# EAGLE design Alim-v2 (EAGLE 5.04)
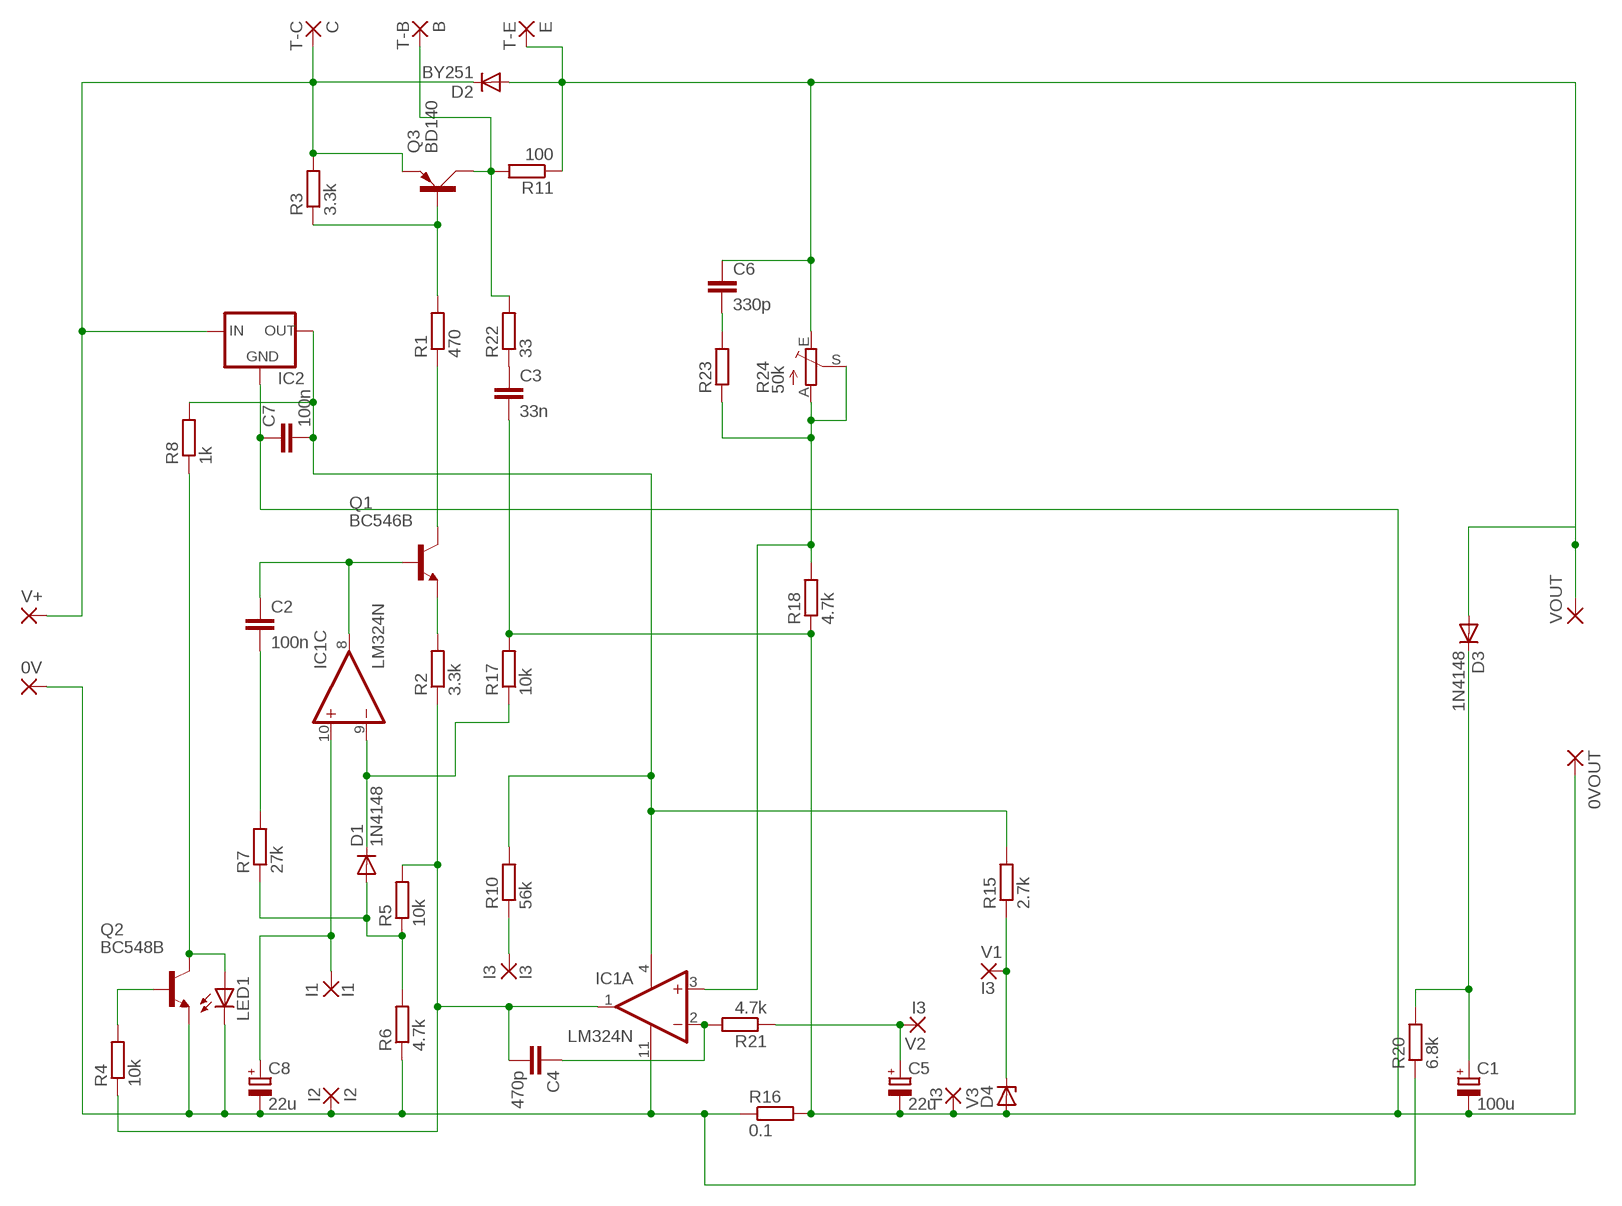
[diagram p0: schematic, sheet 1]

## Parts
0V  3,81/1,4  [3,81/1,4]
0VOUT  3,81/1,4  [3,81/1,4]
B  T-B  WIREPAD3,81/1,4  [3,81/1,4]
C  T-C  WIREPAD3,81/1,4  [3,81/1,4]
C1  100u  CPOL-EUE2.5-5  [E2,5-5]
C2  100n  C-EU025-025X050  [C025-025X050]
C3  33n  C-EU025-025X050  [C025-025X050]
C4  470p  C-EU025-025X050  [C025-025X050]
C5  22u  CPOL-EUE2.5-5  [E2,5-5]
C6  330p  C-EU025-025X050  [C025-025X050]
C7  100n  C-EU025-025X050  [C025-025X050]
C8  22u  CPOL-EUE2.5-5  [E2,5-5]
D1  1N4148  1N4148DO35-10  [DO35-10]
D2  BY251  [DO201-15]
D3  1N4148  1N4148DO35-10  [DO35-10]
D4  ZENER-DIODEDO41Z10  [DO41Z10]
E  T-E  WIREPAD3,81/1,4  [3,81/1,4]
I1  I1  WIREPAD1,6/0,9  [1,6/0,9]
I2  I2  WIREPAD1,6/0,9  [1,6/0,9]
I3  I3  WIREPAD1,6/0,9  [1,6/0,9]
IC1  LM324N  [DIL14]
IC2  78LXX  [78LXX]
LED1  LED5MM  [LED5MM]
Q1  BC546B  [TO92-EBC]
Q2  BC548B  [TO92-EBC]
Q3  BD140  [TO126AV]
R1  470  R-EU_0207/10  [0207/10]
R2  3.3k  R-EU_0207/10  [0207/10]
R3  3.3k  R-EU_0207/10  [0207/10]
R4  10k  R-EU_0207/10  [0207/10]
R5  10k  R-EU_0207/10  [0207/10]
R6  4.7k  R-EU_0207/10  [0207/10]
R7  27k  R-EU_0207/10  [0207/10]
R8  1k  R-EU_0207/10  [0207/10]
R10  56k  R-EU_0207/10  [0207/10]
R11  100  R-EU_0207/10  [0207/10]
R15  2.7k  R-EU_0207/10  [0207/10]
R16  0.1  R-EU_0617/5V  [0617V]
R17  10k  R-EU_0207/10  [0207/10]
R18  4.7k  R-EU_0207/10  [0207/10]
R20  6.8k  R-EU_0207/10  [0207/10]
R21  4.7k  R-EU_0207/10  [0207/10]
R22  33  R-EU_0207/10  [0207/10]
R23  R-EU_0207/10  [0207/10]
R24  50k  TRIM_EU-B64Y  [B64Y]
V1  I3  WIREPAD1,6/0,9  [1,6/0,9]
V2  I3  WIREPAD1,6/0,9  [1,6/0,9]
V3  I3  WIREPAD1,6/0,9  [1,6/0,9]
V+  3,81/1,4  [3,81/1,4]
VOUT  3,81/1,4  [3,81/1,4]

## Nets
N$1: Q3.B R1.2 R3.1
N$2: Q1.C R1.1
N$3: Q1.E R2.2
N$5: Q2.B R4.2
N$6: C4.2 IC1.1(A:OUT) R2.1 R4.1 R5.2
N$7: D1.C IC1.9(C:-IN) R17.1
N$8: 0V.1(P) C8.- I2.1(P) IC1.11(P:V-) LED1.K(C) Q2.E R6.1 R16.1 R20.1
N$9: D1.A R5.1 R6.2 R7.1
N$10: LED1.A Q2.C R8.1
N$11: C.1(P) D2.C IC2.IN Q3.E R3.2 V+.1(P)
N$12: C2.1 IC1.8(C:OUT) Q1.B
N$13: C8.+ I1.1(P) IC1.10(C:+IN)
N$14: I3.1(P) R10.1
N$15: C7.2 IC1.4(P:V+) IC2.OUT R8.2 R10.2 R15.2
N$16: 0VOUT.1(P) C1.- C3.2 C5.- C7.1 D4.A IC2.GND R16.2 R17.2 R18.1 V3.1(P)
N$17: B.1(P) Q3.C R11.2 R22.2
N$18: C6.1 D2.A D3.A E.1(P) R11.1 R24.E VOUT.1(P)
N$20: D4.C R15.1 V1.1(P)
N$21: IC1.3(A:+IN) R18.2 R23.1 R24.A R24.S
N$22: C4.1 IC1.2(A:-IN) R21.2
N$23: C2.2 R7.2
N$25: C1.+ D3.C R20.2
N$26: C3.1 R22.1
N$27: C5.+ R21.1 V2.1(P)
N$29: C6.2 R23.2
Unconnected: IC1.5(B:+IN) IC1.6(B:-IN) IC1.7(B:OUT) IC1.12(D:+IN) IC1.13(D:-IN) IC1.14(D:OUT)

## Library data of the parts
0V 0VOUT V+ VOUT = wirepad:3,81/1,4: THROUGH-HOLE PAD
B C E I1-I3 V1-V3 = wirepad:WIREPAD: Wire PAD connect wire on PCB
C1 C5 C8 = rcl:CPOL-EU: POLARIZED CAPACITOR, European symbol
C2-C4 C6 C7 = rcl:C-EU: CAPACITOR, European symbol
D1 D3 = diode:1N4148: DIODE
D2 = diode:BY251: DIODE
D4 = diode:ZENER-DIODE: Z-Diode
IC1 = linear:LM324: OP AMP
IC2 = v-reg:78LXX: VOLTAGE REGULATOR
LED1 = led:LED: LED
Q1 = transistor-npn:BC546*: NPN Transistor
Q2 = transistor-npn:BC548*: NPN Transistor
Q3 = transistor-power:BD140: PNP TRANSISTOR
R1-R8 R10 R11 R15 R17 R18 R20-R23 = resistor:R-EU_: RESISTOR, European symbol
R16 = rcl:R-EU_: RESISTOR, European symbol
R24 = pot:TRIM_EU-: POTENTIOMETER

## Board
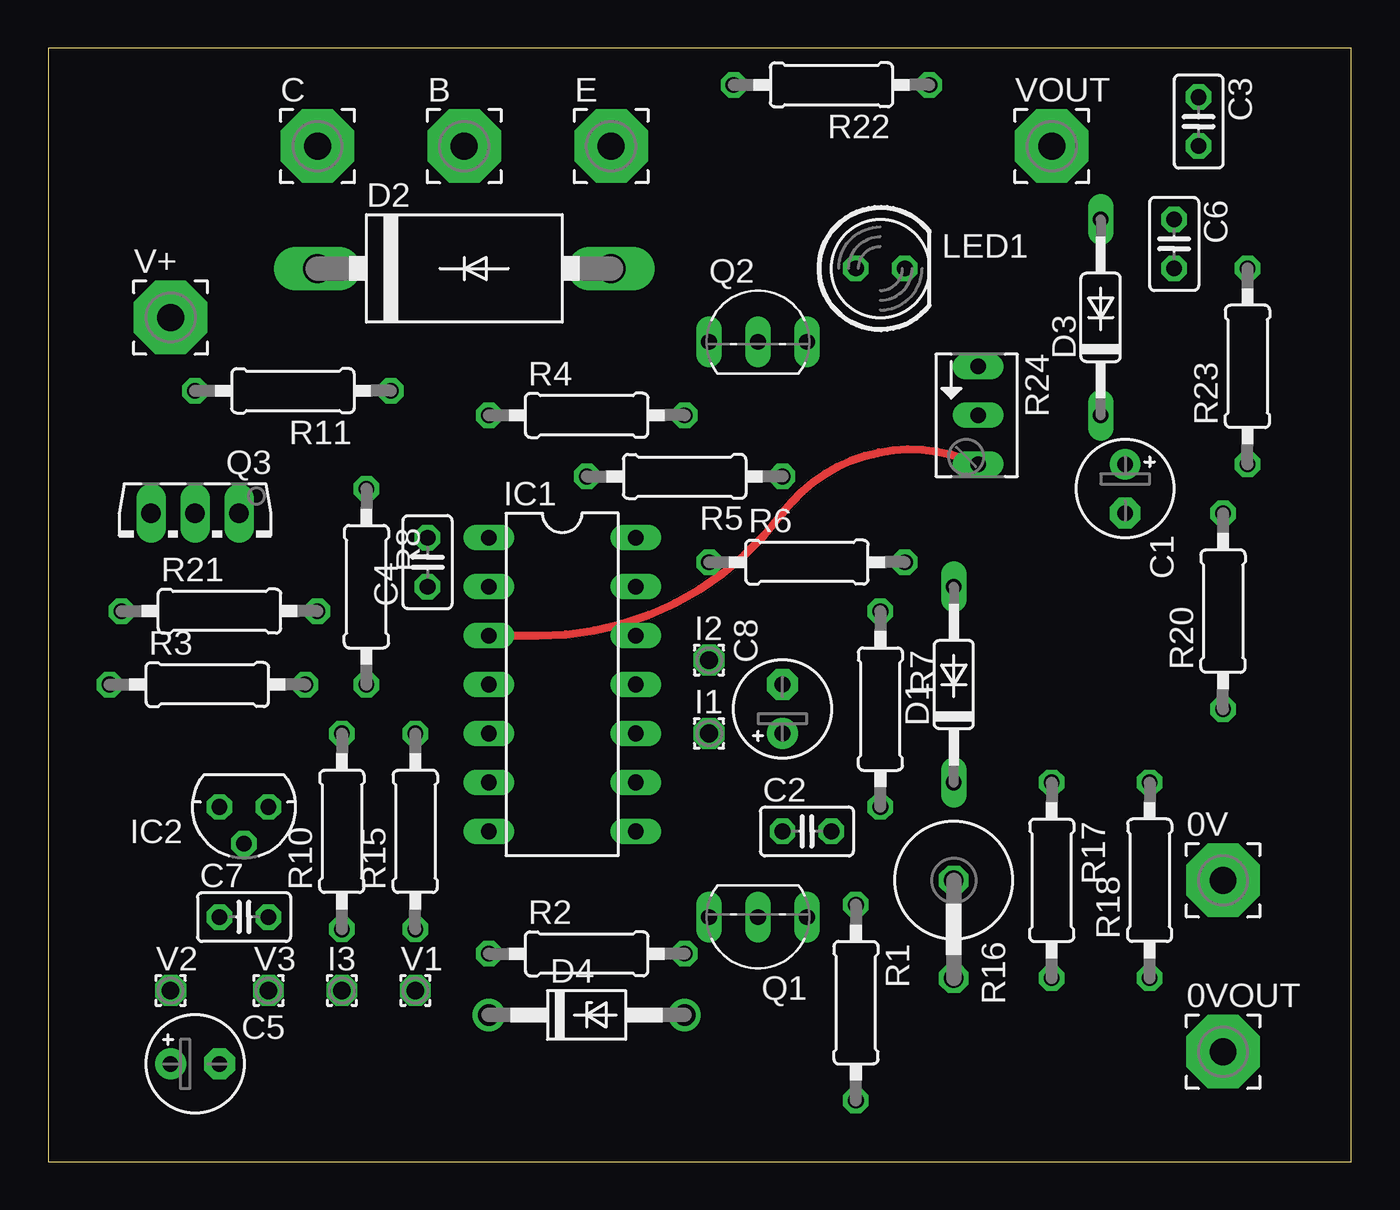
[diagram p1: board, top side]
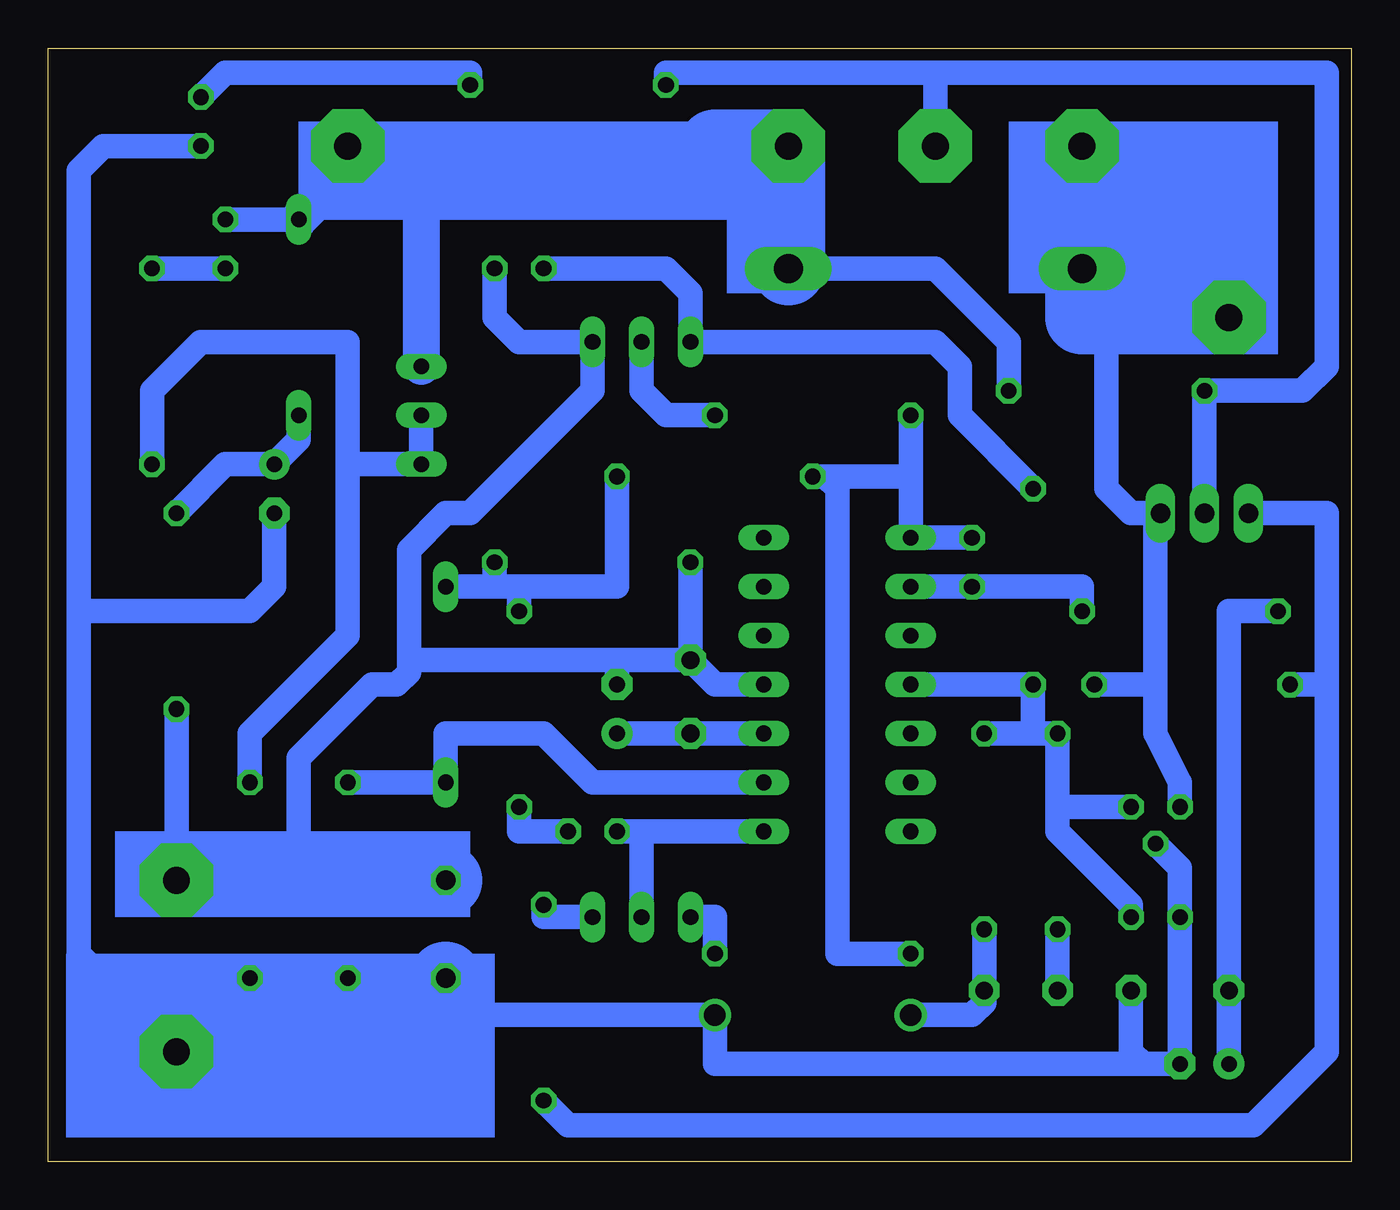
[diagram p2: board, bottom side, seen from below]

Size 67.61 x 57.77 mm. Coordinates in mm from the lower left corner, seen from the top.
Outline: 0,0 67.61,0 67.61,57.77 0,57.77 0,0
Copper layers (1*16): Top 0.035mm / dielectric 1.5mm / Bottom 0.035mm
Design rules "default": minimum track width 10mil, minimum drill 24mil, track to track 8mil, track to pad 8mil, pad to pad 8mil, via to via 8mil, smd to smd 8mil, copper to edge 40mil, drill to drill 8mil, minimum pad ring 10mil, minimum via ring 8mil, stop-mask expansion 4mil, vias tented up to drill 0mil, thermal gap 10mil

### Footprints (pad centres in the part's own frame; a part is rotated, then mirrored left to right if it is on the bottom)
3,81/1,4 = drill 1.397 pad 3.81 octagon: 1 0,0
E2,5-5 = drill 0.813 pad 1.6 round: + -1.27,0 | drill 0.813 pad 1.6 octagon: - 1.27,0
C025-025X050 = drill 0.813 octagon: 1 -1.27,0; 2 1.27,0
DO35-10 = drill 0.813 long: A 5.08,0; C -5.08,0
DO201-15 = drill 1.499 long: A 7.62,0; C -7.62,0
DO41Z10 = drill 1.118 round: A 5.08,0; C -5.08,0
1,6/0,9 = drill 0.914 pad 1.6 octagon: 1 0,0
DIL14 = drill 0.813 long: 1 -7.62,-3.81; 2 -5.08,-3.81; 3 -2.54,-3.81; 4 0,-3.81; 5 2.54,-3.81; 6 5.08,-3.81; 7 7.62,-3.81; 8 7.62,3.81; 9 5.08,3.81; 10 2.54,3.81; 11 0,3.81; 12 -2.54,3.81; 13 -5.08,3.81; 14 -7.62,3.81
78LXX = drill 0.813 octagon: GND 0,1.905; IN 1.27,0; OUT -1.27,0
LED5MM = drill 0.813 octagon: A -1.27,0; K 1.27,0
TO92-EBC = drill 0.813 long: B 0,-1.27; C -2.54,-1.27; E 2.54,-1.27
TO126AV = drill 1.016 long: B 2.286,-1.27; C 0,-1.27; E -2.286,-1.27
0207/10 = drill 0.813 octagon: 1 -5.08,0; 2 5.08,0
0617V = drill 1.016 octagon: 1 -2.54,0; 2 2.54,0
B64Y = drill 0.813 long: A 2.54,0; E -2.54,0; S 0,0

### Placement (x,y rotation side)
0V  60.96,14.6 0 top
0VOUT  60.96,5.71 0 top
B  21.59,52.71 0 top
C  13.97,52.71 0 top
C1  55.88,34.92 270 top
C2  39.37,17.14 0 top
C3  59.69,53.98 270 top
C4  19.68,31.12 90 top
C5  7.62,5.08 0 top
C6  58.42,47.62 270 top
C7  10.16,12.7 0 top
C8  38.1,23.49 90 top
D1  46.99,24.77 90 top
D2  21.59,46.35 0 top
D3  54.61,43.82 90 top
D4  27.94,7.62 0 top
E  29.21,52.71 0 top
I1  34.29,22.23 0 top
I2  34.29,26.03 0 top
I3  15.24,8.89 0 top
IC1  26.67,24.77 270 top
IC2  10.16,18.41 180 top
LED1  43.18,46.35 0 top
Q1  36.83,11.43 180 top
Q2  36.83,43.82 0 top
Q3  7.62,32.38 180 top
R1  41.91,8.25 270 top
R2  27.94,10.8 0 top
R3  8.26,24.77 0 top
R4  27.94,38.73 0 top
R5  33.02,35.56 180 top
R6  39.37,31.12 0 top
R7  43.18,23.49 270 top
R8  16.51,29.84 270 top
R10  15.24,17.14 90 top
R11  12.7,40 180 top
R15  19.05,17.14 90 top
R16  46.99,12.06 270 top
R17  52.07,14.6 270 top
R18  57.15,14.6 90 top
R20  60.96,28.57 90 top
R21  8.89,28.57 0 top
R22  40.64,55.88 180 top
R23  62.23,41.27 90 top
R24  48.26,38.73 270 top
V1  19.05,8.89 0 top
V2  6.35,8.89 0 top
V3  11.43,8.89 0 top
V+  6.35,43.82 0 top
VOUT  52.07,52.71 0 top

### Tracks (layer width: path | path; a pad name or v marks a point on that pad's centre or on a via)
N$1
  Bottom 1.27: Q3.B 1.27,33.66 1.27,24.77 | 1.27,24.77 R3.1 | 1.27,24.77 1.27,5.71 5.08,1.9 40.64,1.9 R1.2
N$2
  Bottom 1.27: Q1.C 41.91,12.7 R1.1
N$3
  Bottom 1.27: R2.2 33.02,12.7 Q1.E
N$5
  Bottom 1.27: R4.2 35.56,38.73 36.83,40 Q2.B
N$6
  Bottom 1.27: R2.1 26.67,10.8 26.67,34.92 27.3,35.56 R5.2 22.86,35.56 22.86,36.2 | 22.86,36.2 IC1.1 C4.2 | 22.86,36.2 R4.1
N$7
  Bottom 1.27: IC1.9 39.37,19.68 41.91,22.23 46.99,22.23 D1.C R17.1
N$8
  Bottom 1.27: LED1.K 44.45,43.82 43.18,42.54 Q2.E 39.37,40 45.72,33.66 46.99,33.66 48.9,31.75 48.9,26.03 | 0V.1 R20.1 | IC1.11 33.02,24.77 I2.1 | 54.61,14.6 54.61,20.95 50.8,24.77 49.53,24.77 48.9,25.4 48.9,26.03 | I2.1 R6.1 I2.1 | I2.1 38.1,26.03 | 38.1,26.03 48.9,26.03 | 38.1,26.03 C8.-
  Bottom 3.81: R16.1 54.61,14.6 0V.1
N$9
  Bottom 1.27: 43.18,29.84 R7.1 | 43.18,29.84 38.1,29.84 R5.1 | 43.18,29.84 44.45,29.84 | 44.45,29.84 D1.A | 44.45,29.84 R6.2
N$10
  Bottom 1.27: R8.1 20.32,38.73 20.32,41.27 21.59,42.54 Q2.C 34.29,45.09 35.56,46.35 LED1.A
N$11
  Bottom 1.27: IC2.IN 8.89,19.68 10.16,22.23 10.16,24.77 | 10.16,24.77 R3.2 | 10.16,24.77 10.16,33.4 Q3.E 11.43,33.66 12.7,34.92 12.7,43.82
  Bottom 3.81: V+.1 12.7,43.82 13.97,43.82 D2.C C.1
N$12
  Bottom 1.27: IC1.8 36.83,17.14 | 36.83,17.14 C2.1 | 36.83,17.14 Q1.B
N$13
  Bottom 1.27: IC1.10 I1.1 C8.+
N$14
  Bottom 1.27: I3.1 R10.1
N$15
  Bottom 1.27: 16.51,22.23 R10.2 15.24,18.41 | 16.51,22.23 R15.2 | 15.24,18.41 15.24,17.14 11.43,13.34 C7.2 | 15.24,18.41 IC2.OUT | IC1.4 R8.2 16.51,22.23
N$16
  Bottom 0.406: 66.04,28.57 66.04,32.38
  Bottom 1.27: C3.2 64.77,52.71 66.04,51.43 66.04,28.57 | 66.04,28.57 66.04,10.8 64.77,9.52 R18.1 R17.2 R16.2 | 46.99,6.98 46.36,7.62 D4.A 33.02,5.08 10.79,5.08 | 10.79,5.08 C5.- C7.1 8.89,15.24 IC2.GND | 10.79,5.08 11.43,5.71 V3.1 | 66.04,28.57 57.15,28.57 55.88,29.84 C1.-
  Bottom 3.81: 0VOUT.1 46.99,5.71 46.99,6.98 R16.2
N$17
  Bottom 1.27: R22.2 35.56,56.51 21.59,56.51 | 21.59,56.51 1.27,56.51 1.27,41.27 2.54,40 R11.2 Q3.C | 21.59,56.51 B.1
N$18
  Bottom 1.27: D3.A C6.1 | D2.A 21.59,46.35 17.78,42.54 R11.1
  Bottom 1.93: 52.07,51.43 D3.A | 48.26,50.8 R24.E
  Bottom 3.81: VOUT.1 52.07,51.43 52.07,50.8 48.26,50.8 33.02,50.8 33.02,52.71 E.1 D2.A
N$20
  Bottom 1.27: R15.1 V1.1 19.05,8.25 19.68,7.62 D4.C
N$21
  Top 0.406: IC1.3 25.4,27.3 arc53 38.1,33.66 arc-78 R24.A
  Bottom 1.27: R23.1 62.23,40 59.69,42.54 52.07,42.54 52.07,36.2 | R18.2 57.15,22.23 52.07,27.3 52.07,36.2 | 52.07,36.2 R24.A R24.S
N$22
  Bottom 1.27: IC1.2 C4.1 13.97,29.84 R21.2
N$23
  Bottom 1.27: C2.2 43.18,17.14 R7.2
N$25
  Bottom 1.27: D3.C 54.61,37.46 C1.+ 58.42,36.2 R20.2
N$26
  Bottom 1.27: R22.1 45.72,56.51 58.42,56.51 C3.1
N$27
  Bottom 1.27: C5.+ V2.1 6.35,28.57 R21.1
N$29
  Bottom 1.27: C6.2 R23.2
(copper drawn outside any net)
  shapes: Bottom area x9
